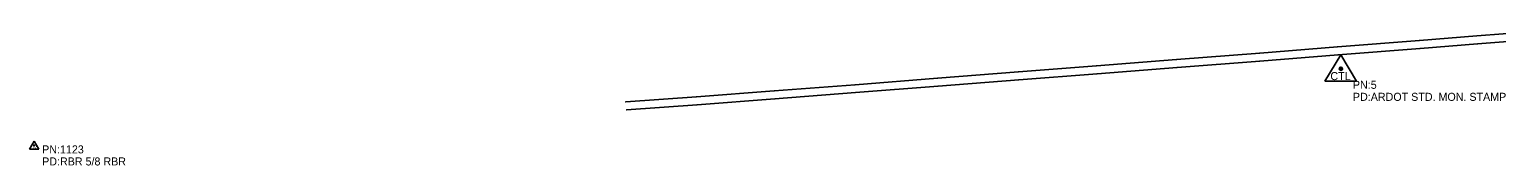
# Model space of a CAD drawing. Extents: x 878399 to 889864, y 1564003 to 1567413.
# Drawn here: x 883085 to 884002, y 1565339 to 1565424 of the extents above; entities that cross this region are included whole.
import ezdxf

# ---------------------------------------------------------------- set-up
doc = ezdxf.new("R2010")
doc.units = 0
for name, color, linetype in [('S_MSC_PT_SYM', 7, 'Continuous'), ('S_PRIMARY_CTL', 7, 'Continuous'), ('S_PRIMARY_CTL_ANNOT', 7, 'Continuous'), ('S_RAILROAD', 7, 'Continuous'), ('S_SECONDARY_CTL', 7, 'Continuous'), ('S_SECONDARY_CTL_ANNOT', 7, 'Continuous')]:
    doc.layers.add(name, color=color, linetype=linetype)

msp = doc.modelspace()

# ---------------------------------------------------------------- linework, layer by layer
at = {"layer": 'S_MSC_PT_SYM'}
for points in [[(883953.48, 1565416.81), (883953.48, 1565416.86), (883953.48, 1565416.81), (883953.43, 1565416.81), (883953.48, 1565416.81), (883953.48, 1565416.76), (883953.48, 1565416.81), (883953.53, 1565416.81)], [(883989.28, 1565419.62), (883989.28, 1565419.67), (883989.28, 1565419.62), (883989.23, 1565419.62), (883989.28, 1565419.62), (883989.28, 1565419.57), (883989.28, 1565419.62), (883989.33, 1565419.62)], [(883853.76, 1565408.97), (883853.76, 1565409.02), (883853.76, 1565408.97), (883853.71, 1565408.97), (883853.76, 1565408.97), (883853.76, 1565408.92), (883853.76, 1565408.97), (883853.81, 1565408.97)], [(883902.2, 1565412.83), (883902.2, 1565412.88), (883902.2, 1565412.83), (883902.15, 1565412.83), (883902.2, 1565412.83), (883902.2, 1565412.78), (883902.2, 1565412.83), (883902.25, 1565412.83)], [(883902.68, 1565407.88), (883902.68, 1565407.93), (883902.68, 1565407.88), (883902.63, 1565407.88), (883902.68, 1565407.88), (883902.68, 1565407.83), (883902.68, 1565407.88), (883902.73, 1565407.88)], [(883953.92, 1565411.89), (883953.92, 1565411.94), (883953.92, 1565411.89), (883953.87, 1565411.89), (883953.92, 1565411.89), (883953.92, 1565411.84), (883953.92, 1565411.89), (883953.97, 1565411.89)], [(883989.77, 1565414.71), (883989.77, 1565414.76), (883989.77, 1565414.71), (883989.72, 1565414.71), (883989.77, 1565414.71), (883989.77, 1565414.66), (883989.77, 1565414.71), (883989.82, 1565414.71)], [(883751.64, 1565401), (883751.64, 1565401.05), (883751.64, 1565401), (883751.59, 1565401), (883751.64, 1565401), (883751.64, 1565400.95), (883751.64, 1565401), (883751.69, 1565401)], [(883801.74, 1565404.9), (883801.74, 1565404.95), (883801.74, 1565404.9), (883801.69, 1565404.9), (883801.74, 1565404.9), (883801.74, 1565404.85), (883801.74, 1565404.9), (883801.79, 1565404.9)], [(883801.97, 1565399.93), (883801.97, 1565399.98), (883801.97, 1565399.93), (883801.92, 1565399.93), (883801.97, 1565399.93), (883801.97, 1565399.88), (883801.97, 1565399.93), (883802.02, 1565399.93)], [(883853.75, 1565404.02), (883853.75, 1565404.07), (883853.75, 1565404.02), (883853.7, 1565404.02), (883853.75, 1565404.02), (883853.75, 1565403.97), (883853.75, 1565404.02), (883853.8, 1565404.02)], [(883600.86, 1565389.26), (883600.86, 1565389.31), (883600.86, 1565389.26), (883600.81, 1565389.26), (883600.86, 1565389.26), (883600.86, 1565389.21), (883600.86, 1565389.26), (883600.91, 1565389.26)], [(883652.37, 1565393.25), (883652.37, 1565393.3), (883652.37, 1565393.25), (883652.32, 1565393.25), (883652.37, 1565393.25), (883652.37, 1565393.2), (883652.37, 1565393.25), (883652.42, 1565393.25)], [(883702.85, 1565397.23), (883702.85, 1565397.28), (883702.85, 1565397.23), (883702.8, 1565397.23), (883702.85, 1565397.23), (883702.85, 1565397.18), (883702.85, 1565397.23), (883702.9, 1565397.23)], [(883703.04, 1565392.28), (883703.04, 1565392.33), (883703.04, 1565392.28), (883702.99, 1565392.28), (883703.04, 1565392.28), (883703.04, 1565392.23), (883703.04, 1565392.28), (883703.09, 1565392.28)], [(883752.01, 1565396.01), (883752.01, 1565396.06), (883752.01, 1565396.01), (883751.96, 1565396.01), (883752.01, 1565396.01), (883752.01, 1565395.96), (883752.01, 1565396.01), (883752.06, 1565396.01)], [(883501.65, 1565381.7), (883501.65, 1565381.75), (883501.65, 1565381.7), (883501.6, 1565381.7), (883501.65, 1565381.7), (883501.65, 1565381.65), (883501.65, 1565381.7), (883501.7, 1565381.7)], [(883550.25, 1565385.38), (883550.25, 1565385.43), (883550.25, 1565385.38), (883550.2, 1565385.38), (883550.25, 1565385.38), (883550.25, 1565385.33), (883550.25, 1565385.38), (883550.3, 1565385.38)], [(883550.67, 1565380.44), (883550.67, 1565380.49), (883550.67, 1565380.44), (883550.62, 1565380.44), (883550.67, 1565380.44), (883550.67, 1565380.39), (883550.67, 1565380.44), (883550.72, 1565380.44)], [(883600.98, 1565384.31), (883600.98, 1565384.36), (883600.98, 1565384.31), (883600.93, 1565384.31), (883600.98, 1565384.31), (883600.98, 1565384.26), (883600.98, 1565384.31), (883601.03, 1565384.31)], [(883652.64, 1565388.33), (883652.64, 1565388.38), (883652.64, 1565388.33), (883652.59, 1565388.33), (883652.64, 1565388.33), (883652.64, 1565388.28), (883652.64, 1565388.33), (883652.69, 1565388.33)], [(883457.44, 1565378.52), (883457.44, 1565378.57), (883457.44, 1565378.52), (883457.39, 1565378.52), (883457.44, 1565378.52), (883457.44, 1565378.47), (883457.44, 1565378.52), (883457.49, 1565378.52)], [(883458.01, 1565373.61), (883458.01, 1565373.66), (883458.01, 1565373.61), (883457.96, 1565373.61), (883458.01, 1565373.61), (883458.01, 1565373.56), (883458.01, 1565373.61), (883458.06, 1565373.61)], [(883502.03, 1565376.78), (883502.03, 1565376.83), (883502.03, 1565376.78), (883501.98, 1565376.78), (883502.03, 1565376.78), (883502.03, 1565376.73), (883502.03, 1565376.78), (883502.08, 1565376.78)]]:
    msp.add_lwpolyline(points, dxfattribs=at)
at = {"layer": 'S_PRIMARY_CTL'}
for p, q in [((883904.39, 1565407.9), (883894.36, 1565391.39)), ((883904.39, 1565407.9), (883914.22, 1565391.39)), ((883894.36, 1565391.39), (883914.22, 1565391.39))]:
    msp.add_line(p, q, dxfattribs=at)
for radius in [1.04, 0.609, 0.344]:
    msp.add_circle((883904.39, 1565399.2), radius, dxfattribs=at)
at = {"layer": 'S_RAILROAD'}
for p, q in [((883953.48, 1565416.81), (883902.2, 1565412.83)), ((883989.28, 1565419.62), (883953.48, 1565416.81)), ((884041.29, 1565423.7), (883989.28, 1565419.62)), ((884041.49, 1565418.76), (883989.77, 1565414.71)), ((883853.76, 1565408.97), (883801.74, 1565404.9)), ((883902.68, 1565407.88), (883853.75, 1565404.02)), ((883902.2, 1565412.83), (883853.76, 1565408.97)), ((883953.92, 1565411.89), (883902.68, 1565407.88)), ((883989.77, 1565414.71), (883953.92, 1565411.89)), ((883751.64, 1565401), (883702.85, 1565397.23)), ((883801.74, 1565404.9), (883751.64, 1565401)), ((883801.97, 1565399.93), (883752.01, 1565396.01)), ((883853.75, 1565404.02), (883801.97, 1565399.93)), ((883600.86, 1565389.26), (883550.25, 1565385.38)), ((883652.37, 1565393.25), (883600.86, 1565389.26)), ((883702.85, 1565397.23), (883652.37, 1565393.25)), ((883703.04, 1565392.28), (883652.64, 1565388.33)), ((883752.01, 1565396.01), (883703.04, 1565392.28)), ((883501.65, 1565381.7), (883457.44, 1565378.52)), ((883550.25, 1565385.38), (883501.65, 1565381.7)), ((883550.67, 1565380.44), (883502.03, 1565376.78)), ((883600.98, 1565384.31), (883550.67, 1565380.44)), ((883652.64, 1565388.33), (883600.98, 1565384.31)), ((883502.03, 1565376.78), (883458.01, 1565373.61))]:
    msp.add_line(p, q, dxfattribs=at)
at = {"layer": 'S_SECONDARY_CTL'}
for p, q in [((883087.73, 1565354.05), (883084.72, 1565349.1)), ((883087.73, 1565354.05), (883090.68, 1565349.1)), ((883084.72, 1565349.1), (883090.68, 1565349.1))]:
    msp.add_line(p, q, dxfattribs=at)
for radius in [0.311, 0.183, 0.103]:
    msp.add_circle((883087.73, 1565351.44), radius, dxfattribs=at)

# ---------------------------------------------------------------- texts
at = {"layer": 'S_PRIMARY_CTL'}
msp.add_text('CTL', height=5, rotation=360, dxfattribs=at).set_placement((883897.8, 1565392.13))
at = {"layer": 'S_PRIMARY_CTL_ANNOT'}
for s, p in [('PN:5', (883911.89, 1565386.7)), ('PD:ARDOT STD. MON. STAMPED PN:5', (883911.89, 1565379.2))]:
    msp.add_text(s, height=5, dxfattribs=at).set_placement(p)
at = {"layer": 'S_SECONDARY_CTL'}
msp.add_text('TV', height=1.5, rotation=360, dxfattribs=at).set_placement((883086.53, 1565349.43))
at = {"layer": 'S_SECONDARY_CTL_ANNOT'}
for s, p in [('PN:1123', (883092.73, 1565346.44)), ('PD:RBR 5/8 RBR', (883092.73, 1565338.94))]:
    msp.add_text(s, height=5, dxfattribs=at).set_placement(p)

doc.saveas('drawing.dxf')
